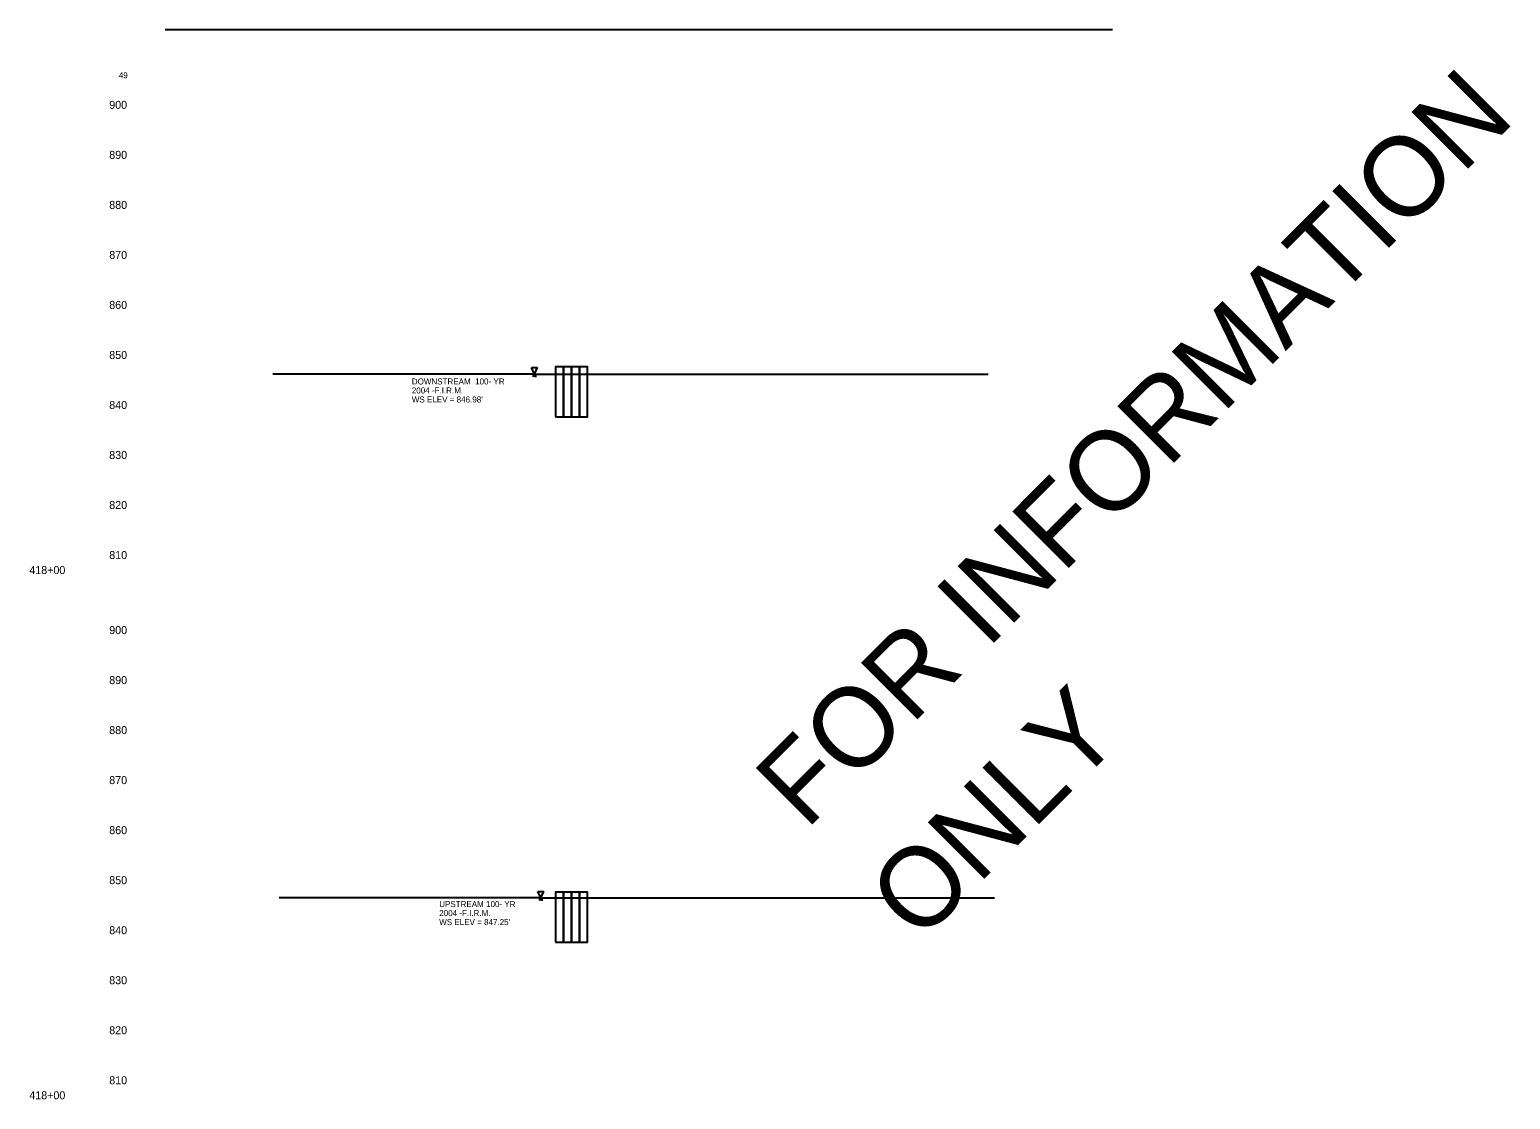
# Model space of a CAD drawing. Extents: x 16992642 to 16995679, y 12627721 to 12628791.
# Drawn here: x 16994199 to 16995679, y 12627721 to 12628791 of the extents above; entities that cross this region are included whole.
import ezdxf

# ---------------------------------------------------------------- set-up
doc = ezdxf.new("R2010")
doc.units = 0
for name, color, linetype in [('Default', 7, 'Continuous'), ('RD_EX_DR_Pipe', 7, 'Continuous'), ('RD_PD_Final_TrvlWay', 7, 'Continuous'), ('RD_SHT_Logo', 7, 'Continuous'), ('RD_SHT_TX', 7, 'Continuous'), ('RD_TX_Drainage', 7, 'Continuous')]:
    doc.layers.add(name, color=color, linetype=linetype)

msp = doc.modelspace()

# ---------------------------------------------------------------- linework, layer by layer
at = {"layer": 'RD_EX_DR_Pipe'}
for points in [[(16994724.8, 12628403.6), (16994732.8, 12628403.6), (16994732.8, 12628453.6), (16994724.8, 12628453.6)], [(16994732.8, 12628403.6), (16994740.8, 12628403.6), (16994740.8, 12628453.6), (16994732.8, 12628453.6)], [(16994740.8, 12628403.6), (16994748.8, 12628403.6), (16994748.8, 12628453.6), (16994740.8, 12628453.6)], [(16994748.8, 12628403.6), (16994756.8, 12628403.6), (16994756.8, 12628453.6), (16994748.8, 12628453.6)], [(16994724.8, 12627878.6), (16994732.8, 12627878.6), (16994732.8, 12627928.6), (16994724.8, 12627928.6)], [(16994732.8, 12627878.6), (16994740.8, 12627878.6), (16994740.8, 12627928.6), (16994732.8, 12627928.6)], [(16994740.8, 12627878.6), (16994748.8, 12627878.6), (16994748.8, 12627928.6), (16994740.8, 12627928.6)], [(16994748.8, 12627878.6), (16994756.8, 12627878.6), (16994756.8, 12627928.6), (16994748.8, 12627928.6)]]:
    msp.add_lwpolyline(points, close=True, dxfattribs=at)
at = {"layer": 'RD_PD_Final_TrvlWay'}
msp.add_line((16994334.6, 12628790.8), (16995281.6, 12628790.8), dxfattribs=at)
at = {"layer": 'RD_TX_Drainage'}
for p, q in [((16994704, 12628446.5), (16994442.3, 12628446.5)), ((16994704, 12628446.5), (16994701, 12628452.9)), ((16994701, 12628452.9), (16994707, 12628452.9)), ((16994704, 12628444.5), (16994702, 12628444.5)), ((16994704, 12628446.5), (16994707, 12628452.9)), ((16994704, 12628446.5), (16995157.4, 12628446.5)), ((16994704, 12628444.5), (16994706, 12628444.5)), ((16994710.2, 12627922.9), (16994707.2, 12627929.3)), ((16994707.2, 12627929.3), (16994713.2, 12627929.3)), ((16994710.2, 12627922.9), (16994713.2, 12627929.3)), ((16994710.2, 12627922.9), (16994448.6, 12627922.9)), ((16994710.2, 12627922.9), (16994705.9, 12627922.9)), ((16994710.2, 12627920.9), (16994708.2, 12627920.9)), ((16994710.2, 12627922.9), (16994714.5, 12627922.9)), ((16994710.2, 12627922.9), (16995163.7, 12627922.9)), ((16994710.2, 12627920.9), (16994712.2, 12627920.9))]:
    msp.add_line(p, q, dxfattribs=at)

# ---------------------------------------------------------------- texts
at = {"layer": 'Default'}
for s, p in [('900', (16994278.7, 12628711.6)), ('890', (16994278.7, 12628661.6)), ('880', (16994278.7, 12628611.6)), ('870', (16994278.7, 12628561.6)), ('860', (16994278.7, 12628511.6)), ('850', (16994278.7, 12628461.6)), ('840', (16994278.7, 12628411.6)), ('830', (16994278.7, 12628361.6)), ('820', (16994278.7, 12628311.6)), ('810', (16994278.7, 12628261.6)), ('418+00', (16994198.8, 12628246.6)), ('900', (16994278.7, 12628186.6)), ('890', (16994278.7, 12628136.6)), ('880', (16994278.7, 12628086.6)), ('870', (16994278.7, 12628036.6)), ('860', (16994278.7, 12627986.6)), ('850', (16994278.7, 12627936.6)), ('840', (16994278.7, 12627886.6)), ('830', (16994278.7, 12627836.6)), ('820', (16994278.7, 12627786.6)), ('810', (16994278.7, 12627736.6)), ('418+00', (16994198.8, 12627721.6))]:
    msp.add_text(s, height=8, dxfattribs=at).set_placement(p)
at = {"layer": 'RD_SHT_Logo'}
for s, p in [('FOR INFORMATION', (16994975.5, 12627990.1)), ('ONLY', (16995088.6, 12627876.9))]:
    msp.add_text(s, height=80, rotation=45, dxfattribs=at).set_placement(p)
at = {"layer": 'RD_SHT_TX'}
msp.add_text('49', height=6, dxfattribs=at).set_placement((16994288.3, 12628742.1))
at = {"layer": 'RD_TX_Drainage'}
for s, p in [('2004 -F.I.R.M.', (16994581.2, 12628427.1)), ('DOWNSTREAM  100- YR ', (16994581.2, 12628436.1)), ("WS ELEV = 846.98' ", (16994581.2, 12628418.1)), ('2004 -F.I.R.M. ', (16994608.6, 12627904.7)), ('UPSTREAM 100- YR ', (16994608.6, 12627913.7)), ("WS ELEV = 847.25'", (16994608.6, 12627895.7))]:
    msp.add_text(s, height=6, dxfattribs=at).set_placement(p)

doc.saveas('drawing.dxf')
